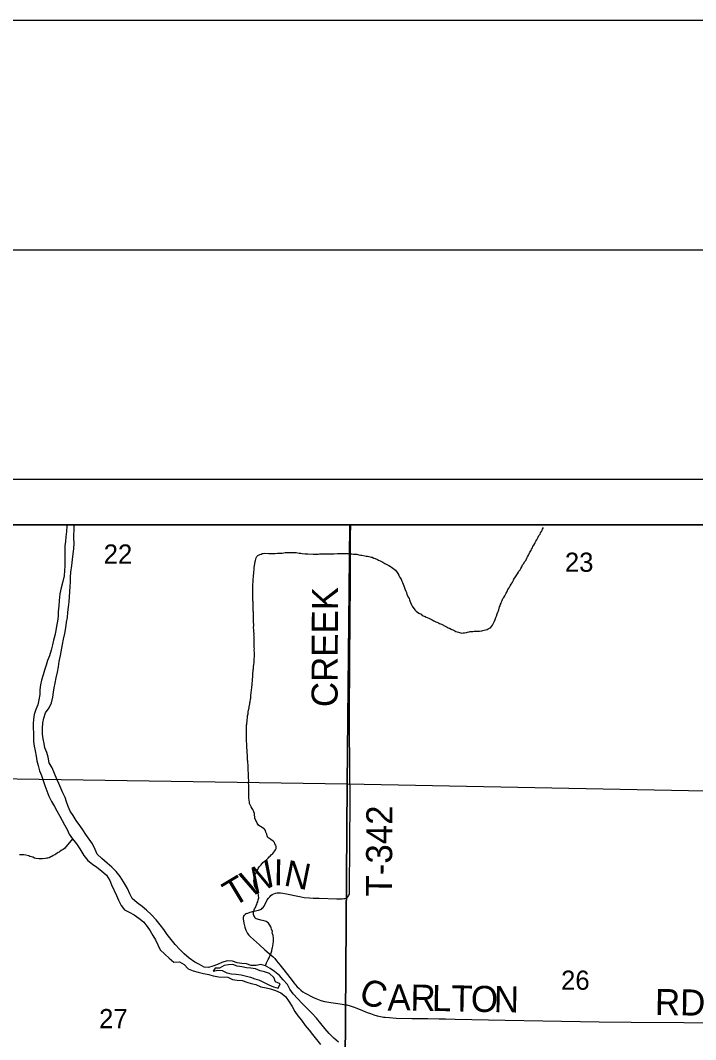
# Model space of a CAD drawing. Extents: x 0 to 34, y 0 to 22.
# Drawn here: x 6.788 to 8.26, y 19.778 to 22 of the extents above; entities that cross this region are included whole.
import ezdxf

# ---------------------------------------------------------------- set-up
doc = ezdxf.new("R2010")
doc.units = 0
for name, color, linetype in [('GM_X_Corporation', 7, 'Continuous'), ('GM_X_Major_River', 7, 'Continuous'), ('GM_X_Minor_River', 7, 'Continuous'), ('GM_X_Section_Text', 7, 'Continuous'), ('GM_X_Township_Road', 7, 'Continuous'), ('GM_X_Township_Road_Text', 7, 'Continuous'), ('SH_Border', 7, 'Continuous'), ('SH_Cut_Line', 7, 'Continuous'), ('SH_Data', 7, 'Continuous')]:
    doc.layers.add(name, color=color, linetype=linetype)

msp = doc.modelspace()

# ---------------------------------------------------------------- linework, layer by layer
at = {"layer": 'GM_X_Corporation'}
msp.add_lwpolyline([(8.9, 20.9), (3.5231, 20.9), (3.5228, 20.8664), (3.5224, 20.8347), (3.5214, 20.7384), (3.5203, 20.6635), (3.5197, 20.5949), (3.5191, 20.549), (3.5181, 20.4924), (3.5169, 20.4148), (3.5163, 20.3526), (3.5155, 20.3135), (3.5145, 20.2333), (3.5137, 20.1344), (3.5125, 20.0737), (3.5112, 20.0053), (3.511, 19.9493), (3.5095, 19.8637), (3.5082, 19.7748)], dxfattribs=at)
for points in [[(7.5063, 20.9), (6.4979, 20.9), (6.4927, 20.3511), (7.5004, 20.336)], [(8.5096, 20.9), (7.5063, 20.9), (7.5004, 20.336), (8.5046, 20.316)], [(6.4927, 20.3511), (7.5004, 20.336), (7.4935, 19.3206), (6.4855, 19.3379)], [(7.5004, 20.336), (8.5046, 20.316), (8.496, 19.3116), (7.4935, 19.3206)]]:
    msp.add_lwpolyline(points, close=True, dxfattribs=at)
at = {"layer": 'GM_X_Major_River'}
for points in [[(6.89, 20.9), (6.8897, 20.8971), (6.8887, 20.8861), (6.8873, 20.8743), (6.8864, 20.8641), (6.8851, 20.8543), (6.8849, 20.8425), (6.8851, 20.833), (6.8852, 20.8205), (6.885, 20.811), (6.8845, 20.8007), (6.8835, 20.7893), (6.8806, 20.7765), (6.8769, 20.7633), (6.8744, 20.75), (6.873, 20.7356), (6.872, 20.7235), (6.871, 20.711), (6.8709, 20.7015), (6.8695, 20.6901), (6.8674, 20.6795), (6.8653, 20.6697), (6.8633, 20.6591), (6.8608, 20.6489), (6.8587, 20.639), (6.8551, 20.6273), (6.8518, 20.6145), (6.8478, 20.6043), (6.8442, 20.5945), (6.8406, 20.5835), (6.8382, 20.5733), (6.8345, 20.5616), (6.8324, 20.5518), (6.8311, 20.5408), (6.8305, 20.5302), (6.8284, 20.5185), (6.8263, 20.5082), (6.822, 20.4977), (6.8187, 20.4867), (6.8166, 20.4765), (6.8161, 20.4667), (6.8159, 20.4572), (6.8168, 20.4469), (6.8173, 20.4279), (6.8186, 20.418), (6.8207, 20.4073), (6.8227, 20.3963), (6.8244, 20.3856), (6.8269, 20.3757), (6.8301, 20.3642), (6.8341, 20.3539), (6.8377, 20.3432), (6.842, 20.3317), (6.846, 20.3206), (6.8507, 20.3088), (6.8562, 20.2973), (6.8625, 20.2865), (6.868, 20.2766), (6.8742, 20.2654), (6.8845, 20.2463), (6.89, 20.2359), (6.8947, 20.2263), (6.9017, 20.2155), (6.9103, 20.2051), (6.918, 20.194), (6.9269, 20.1794), (6.9354, 20.1686), (6.9455, 20.1604), (6.9552, 20.1538), (6.965, 20.1464), (6.9758, 20.1367), (6.9835, 20.1252), (6.9872, 20.1152), (6.9981, 20.0922), (7.0025, 20.0819), (7.008, 20.0708), (7.0154, 20.0612), (7.0255, 20.0556), (7.036, 20.0501), (7.0465, 20.0431), (7.057, 20.0346), (7.0648, 20.0245), (7.0711, 20.0149), (7.0769, 20.0053), (7.0825, 19.9957), (7.0876, 19.985), (7.0931, 19.9739), (7.1031, 19.9642), (7.1128, 19.9553), (7.1229, 19.9468), (7.1351, 19.9477), (7.1456, 19.9418), (7.1541, 19.9321)], [(7.261, 19.9457), (7.2504, 19.9489), (7.2391, 19.9495), (7.2276, 19.9459), (7.2177, 19.942), (7.2081, 19.9383), (7.1982, 19.9355), (7.1887, 19.936), (7.1786, 19.9415), (7.1688, 19.9467), (7.1561, 19.9553), (7.1453, 19.9649), (7.1352, 19.975), (7.1259, 19.9854), (7.1166, 19.9966), (7.1085, 20.007), (7.1007, 20.0182), (7.0929, 20.0282), (7.084, 20.0394), (7.0732, 20.0506), (7.0635, 20.0603), (7.0534, 20.0684), (7.043, 20.0766), (7.0318, 20.0855), (7.027, 20.0959), (7.0215, 20.1077), (7.0131, 20.1223), (7.0057, 20.1339), (6.9968, 20.1443), (6.9875, 20.1543), (6.9774, 20.1629), (6.9655, 20.173), (6.9554, 20.1823), (6.951, 20.1926), (6.9452, 20.2049), (6.9382, 20.2153), (6.9311, 20.2253), (6.9245, 20.2353), (6.9182, 20.2449), (6.9101, 20.2556), (6.9031, 20.2664), (6.8972, 20.2764), (6.8928, 20.286), (6.8892, 20.2963), (6.8856, 20.3059), (6.8812, 20.3158), (6.8765, 20.3262), (6.8721, 20.3365), (6.8677, 20.3461), (6.8576, 20.3706), (6.8509, 20.3813), (6.8492, 20.3935), (6.846, 20.4038), (6.842, 20.4141), (6.8403, 20.4237), (6.8382, 20.434), (6.8369, 20.4439), (6.8364, 20.456), (6.8374, 20.4685), (6.8394, 20.4788), (6.8434, 20.4905), (6.8509, 20.5017), (6.8564, 20.5126), (6.8589, 20.5243), (6.8606, 20.5353), (6.8623, 20.5452), (6.864, 20.5554), (6.8665, 20.5671), (6.869, 20.5792), (6.8711, 20.5906), (6.8732, 20.6023), (6.8761, 20.6152), (6.8803, 20.6394), (6.8825, 20.6508), (6.8853, 20.6636), (6.8875, 20.6761), (6.8892, 20.6882), (6.8909, 20.6984), (6.8919, 20.7098), (6.8932, 20.7208), (6.8946, 20.7326), (6.8955, 20.7432), (6.8967, 20.7659), (6.8973, 20.7758), (6.8975, 20.7861), (6.8984, 20.797), (6.9002, 20.8118), (6.902, 20.8247), (6.9033, 20.8372), (6.9047, 20.8482), (6.9053, 20.86), (6.9051, 20.8713), (6.9056, 20.896), (6.9054, 20.9)], [(7.1541, 19.9321), (7.1651, 19.9281), (7.176, 19.9253), (7.1873, 19.9224), (7.1987, 19.9199), (7.2085, 19.9171), (7.2206, 19.9146), (7.2407, 19.9142), (7.2508, 19.9091), (7.2607, 19.9074), (7.2717, 19.9068), (7.2815, 19.9036), (7.2913, 19.9007), (7.3015, 19.8983), (7.3124, 19.8935), (7.3237, 19.891), (7.3336, 19.8885), (7.3441, 19.8853), (7.3558, 19.8798), (7.3663, 19.872), (7.3744, 19.8604), (7.3803, 19.8505), (7.3865, 19.8397), (7.3932, 19.8301), (7.4006, 19.8205), (7.4091, 19.8089), (7.4177, 19.7989), (7.4251, 19.7893), (7.434, 19.7785), (7.4425, 19.7673)], [(7.2083, 19.9273), (7.2186, 19.9294), (7.2284, 19.9288), (7.2382, 19.9234), (7.2484, 19.9213), (7.2587, 19.9211), (7.2692, 19.919), (7.2896, 19.914), (7.2994, 19.9108), (7.3096, 19.9076), (7.3194, 19.9029), (7.3299, 19.8973), (7.3401, 19.893), (7.3503, 19.8901), (7.3543, 19.8999), (7.3445, 19.9039), (7.3409, 19.9138), (7.3311, 19.9224), (7.3206, 19.926), (7.3108, 19.9281), (7.3006, 19.9321), (7.2908, 19.9338), (7.2813, 19.9343), (7.2707, 19.9364), (7.2609, 19.9385), (7.2511, 19.9417), (7.2416, 19.9411), (7.2321, 19.9398)], [(7.2321, 19.9398), (7.2225, 19.9335), (7.213, 19.9337), (7.2083, 19.9273)], [(7.4817, 19.7727), (7.4712, 19.7812), (7.4612, 19.7916), (7.4519, 19.8024), (7.443, 19.8132), (7.4333, 19.8248), (7.424, 19.8352), (7.4128, 19.8464), (7.4024, 19.8569), (7.3931, 19.8669), (7.3827, 19.8778), (7.3753, 19.8878), (7.3702, 19.8985), (7.3609, 19.9082), (7.3527, 19.9178), (7.3422, 19.9264), (7.3325, 19.9334), (7.3227, 19.9392), (7.3122, 19.9421), (7.3019, 19.9396), (7.2916, 19.9394), (7.2814, 19.943), (7.2712, 19.944), (7.261, 19.9457)]]:
    msp.add_lwpolyline(points, dxfattribs=at)
at = {"layer": 'GM_X_Minor_River'}
for points in [[(7.8348, 20.7273), (7.836, 20.7299), (7.8369, 20.7326), (7.8385, 20.7356), (7.8397, 20.7394), (7.8417, 20.7416), (7.8438, 20.7457), (7.8466, 20.751), (7.8482, 20.7532), (7.8502, 20.757), (7.8507, 20.7592), (7.8538, 20.7633), (7.8555, 20.7671), (7.8575, 20.7712), (7.8599, 20.7738), (7.8627, 20.7795), (7.8639, 20.7817), (7.8671, 20.7866), (7.8687, 20.7888), (7.8715, 20.7937), (7.8739, 20.7971), (7.8748, 20.7993), (7.8775, 20.8023), (7.8788, 20.8053), (7.8808, 20.8087), (7.8828, 20.8128), (7.8848, 20.8154), (7.8876, 20.8207), (7.8896, 20.8229), (7.8917, 20.8274), (7.8933, 20.8308), (7.8953, 20.8345), (7.8969, 20.8368), (7.8985, 20.8409), (7.9013, 20.8443), (7.9022, 20.8473), (7.9042, 20.8503), (7.9054, 20.8529), (7.9074, 20.8559), (7.9094, 20.8593), (7.9102, 20.8615), (7.9119, 20.8649), (7.9139, 20.8679), (7.9151, 20.8705), (7.9167, 20.8732), (7.9183, 20.8769), (7.9207, 20.8803), (7.9219, 20.8829), (7.9239, 20.8859), (7.9252, 20.8885), (7.9264, 20.8912), (7.928, 20.8942)], [(7.2974, 20.6602), (7.2975, 20.6629), (7.2973, 20.6678), (7.2969, 20.6701), (7.2967, 20.6774), (7.2968, 20.6812), (7.2969, 20.6834), (7.2967, 20.6884), (7.2963, 20.6911), (7.2964, 20.6933), (7.2961, 20.6983), (7.2962, 20.7013), (7.296, 20.707), (7.2961, 20.7097), (7.2957, 20.712), (7.2959, 20.7177), (7.2956, 20.7215), (7.2957, 20.7241), (7.2954, 20.7295), (7.2955, 20.7325), (7.2952, 20.7348), (7.2949, 20.7382), (7.295, 20.7428), (7.2947, 20.7451), (7.2949, 20.7515), (7.2946, 20.7569), (7.295, 20.772), (7.2955, 20.7743), (7.2957, 20.7823), (7.2962, 20.7872), (7.2967, 20.7903), (7.2968, 20.7941), (7.2968, 20.7967), (7.2978, 20.8035), (7.2979, 20.8066), (7.2988, 20.8119), (7.2993, 20.8153), (7.3002, 20.8206), (7.3006, 20.8228), (7.3023, 20.8281), (7.3035, 20.8311), (7.3055, 20.8337), (7.3102, 20.8359), (7.3129, 20.8366), (7.3152, 20.8377), (7.3175, 20.8376), (7.3214, 20.8383), (7.3298, 20.8381), (7.3344, 20.8376), (7.3371, 20.8379), (7.3402, 20.8378), (7.3437, 20.8381), (7.3487, 20.8384), (7.3529, 20.8387), (7.3552, 20.8386), (7.3587, 20.8389), (7.3625, 20.8392), (7.3656, 20.8399), (7.3698, 20.8398), (7.3729, 20.8401), (7.3891, 20.8397), (7.3959, 20.8388), (7.3998, 20.8383), (7.4021, 20.8378), (7.4086, 20.8373), (7.4147, 20.8368), (7.4266, 20.8365), (7.4301, 20.8364), (7.4339, 20.8367), (7.437, 20.8366), (7.4405, 20.8369), (7.4431, 20.8368), (7.4466, 20.8371), (7.4516, 20.837), (7.4555, 20.8373), (7.4624, 20.8371), (7.4662, 20.8374), (7.4716, 20.8373), (7.4793, 20.8375), (7.4831, 20.8378), (7.4862, 20.8377), (7.4893, 20.8376), (7.4916, 20.8379), (7.5027, 20.8377), (7.5077, 20.8372), (7.5104, 20.8371), (7.5142, 20.8366), (7.5165, 20.8366), (7.5188, 20.8361), (7.5219, 20.8361), (7.5257, 20.8352), (7.5299, 20.8343), (7.5326, 20.8339), (7.5387, 20.8326), (7.5421, 20.8321), (7.5448, 20.8317), (7.5479, 20.8313), (7.5528, 20.83), (7.5551, 20.8296), (7.5586, 20.8279), (7.5612, 20.8267)], [(7.5612, 20.8267), (7.5665, 20.8247), (7.5688, 20.8231), (7.5722, 20.8215), (7.5753, 20.8203), (7.5783, 20.8187), (7.5825, 20.8163), (7.5866, 20.814), (7.5912, 20.8116), (7.5949, 20.8092), (7.5972, 20.808), (7.6002, 20.806), (7.6032, 20.8037), (7.6059, 20.8017), (7.6096, 20.7963), (7.6107, 20.794), (7.6129, 20.7905), (7.6154, 20.7855), (7.618, 20.7816), (7.6195, 20.7778), (7.6209, 20.7747), (7.6227, 20.7709), (7.6242, 20.7674), (7.6249, 20.7651), (7.6263, 20.7609), (7.6285, 20.7559), (7.6299, 20.7525), (7.6306, 20.749), (7.6335, 20.7429), (7.6353, 20.7394), (7.6361, 20.7371), (7.6371, 20.7348), (7.6382, 20.731), (7.6407, 20.7256), (7.6422, 20.7229), (7.6433, 20.7206), (7.6467, 20.7171), (7.6478, 20.7148), (7.6508, 20.7124), (7.6534, 20.7101), (7.6568, 20.7077), (7.6617, 20.7053), (7.664, 20.703), (7.6704, 20.7005), (7.6727, 20.6993), (7.675, 20.6985), (7.6784, 20.6969), (7.686, 20.6929), (7.6894, 20.6913), (7.6939, 20.6889), (7.6962, 20.6881), (7.6993, 20.6865), (7.7019, 20.6849), (7.7057, 20.6837), (7.7156, 20.6785), (7.7182, 20.6773), (7.7205, 20.6757), (7.7232, 20.6749), (7.7269, 20.6729), (7.7323, 20.6705), (7.7349, 20.6693), (7.7372, 20.6681), (7.7402, 20.6673), (7.7429, 20.6661), (7.7452, 20.6656), (7.7482, 20.6648), (7.7505, 20.6644), (7.7532, 20.6647), (7.7563, 20.665), (7.7602, 20.6656), (7.7625, 20.6664), (7.766, 20.667), (7.7687, 20.6677), (7.7718, 20.668), (7.7745, 20.668), (7.7772, 20.6683), (7.7821, 20.6682), (7.7864, 20.6684), (7.7891, 20.6687), (7.7937, 20.6694), (7.7964, 20.6697), (7.7991, 20.6704), (7.8018, 20.6715), (7.8053, 20.6725), (7.808, 20.6736), (7.8104, 20.6751), (7.8131, 20.6761), (7.8151, 20.6784), (7.8171, 20.6817), (7.8195, 20.6859), (7.8212, 20.6904), (7.8228, 20.6938), (7.8244, 20.6983), (7.8261, 20.7013), (7.8277, 20.7066), (7.8286, 20.7096), (7.8302, 20.713), (7.831, 20.7152), (7.8327, 20.7213), (7.834, 20.7239), (7.8348, 20.7273)], [(7.3128, 20.2421), (7.3098, 20.2437), (7.3075, 20.2453), (7.3057, 20.2476), (7.3046, 20.2503), (7.3027, 20.2534), (7.3017, 20.256), (7.2995, 20.2607), (7.2995, 20.2629), (7.2989, 20.2679), (7.2982, 20.2709), (7.2968, 20.2744), (7.2961, 20.2767), (7.2946, 20.2794), (7.2935, 20.2817), (7.2913, 20.2859), (7.2895, 20.2887), (7.288, 20.2925), (7.2873, 20.2952), (7.2867, 20.3005), (7.2864, 20.3036), (7.2865, 20.3058), (7.2862, 20.3112), (7.2863, 20.3134), (7.286, 20.3157), (7.2862, 20.3252), (7.2859, 20.3275), (7.286, 20.3321), (7.2858, 20.3378), (7.2859, 20.3427), (7.2857, 20.3488), (7.2858, 20.3515), (7.2855, 20.3545), (7.2852, 20.3579), (7.285, 20.3652), (7.2847, 20.3697), (7.2844, 20.3732), (7.2845, 20.3758), (7.2839, 20.3827), (7.284, 20.3853), (7.2836, 20.3876), (7.2834, 20.3933), (7.2835, 20.3964), (7.2832, 20.399), (7.2829, 20.4025), (7.2827, 20.4093), (7.2821, 20.4143), (7.2821, 20.4173), (7.2815, 20.4227), (7.2813, 20.4287), (7.281, 20.4314), (7.2811, 20.4379), (7.2808, 20.4409), (7.2811, 20.4497), (7.2812, 20.4527), (7.2814, 20.4633), (7.2819, 20.466), (7.282, 20.4683), (7.2824, 20.4717), (7.2826, 20.4762), (7.283, 20.4789), (7.2835, 20.4842), (7.2844, 20.4884), (7.2849, 20.4906), (7.2849, 20.4929), (7.2862, 20.499), (7.2867, 20.5016), (7.2871, 20.5039), (7.2885, 20.5103), (7.2885, 20.5126), (7.2893, 20.5148), (7.2899, 20.5205), (7.2903, 20.5228), (7.2908, 20.5277), (7.2914, 20.5346), (7.2923, 20.5391), (7.2925, 20.5467), (7.2934, 20.5512), (7.2935, 20.5558), (7.294, 20.5588), (7.294, 20.5615), (7.2941, 20.5638), (7.2946, 20.5691), (7.2951, 20.5729), (7.2952, 20.5759), (7.2957, 20.5812), (7.2958, 20.5839), (7.2962, 20.5861), (7.2967, 20.5903), (7.2973, 20.5964), (7.2977, 20.5994), (7.2983, 20.6214), (7.2981, 20.6268), (7.2982, 20.6302), (7.2979, 20.6329), (7.2981, 20.6416), (7.2979, 20.6469), (7.2979, 20.6492), (7.2977, 20.6553), (7.2978, 20.6576), (7.2974, 20.6602)], [(7.3227, 19.9392), (7.3237, 19.9434), (7.3245, 19.9457), (7.3269, 19.9498), (7.3282, 19.9525), (7.3302, 19.9566), (7.3314, 19.9588), (7.3326, 19.9618), (7.3343, 19.9652), (7.3355, 19.9698), (7.3364, 19.972), (7.3372, 19.9766), (7.3377, 19.9792), (7.3385, 19.9815), (7.3395, 19.9875), (7.34, 19.9917), (7.3401, 19.997), (7.3398, 19.9993), (7.3392, 20.005), (7.3374, 20.0111), (7.3375, 20.0138), (7.3357, 20.0188), (7.3346, 20.0218), (7.3339, 20.0241), (7.3321, 20.0276), (7.3302, 20.0299), (7.3287, 20.0323), (7.3265, 20.0338), (7.3242, 20.0354), (7.3216, 20.0366), (7.3189, 20.0374), (7.3162, 20.0379), (7.3124, 20.0387), (7.3101, 20.0392), (7.3074, 20.0396), (7.3048, 20.0404), (7.3021, 20.0416), (7.2998, 20.0432), (7.2984, 20.0463), (7.2969, 20.0486), (7.2962, 20.0509), (7.2963, 20.0532), (7.2967, 20.0558), (7.2972, 20.0581), (7.2988, 20.063), (7.3004, 20.066), (7.3021, 20.0702), (7.3037, 20.0724), (7.3046, 20.0762), (7.3058, 20.0788), (7.3066, 20.0826), (7.3071, 20.0849), (7.3079, 20.0875), (7.3076, 20.0913), (7.3073, 20.094), (7.3066, 20.0966), (7.3048, 20.1001), (7.3034, 20.1047), (7.3019, 20.1074), (7.3001, 20.1101), (7.2986, 20.1132), (7.2983, 20.1162), (7.2976, 20.1197), (7.2974, 20.1246), (7.2975, 20.1277), (7.2984, 20.1333), (7.2996, 20.1371), (7.3013, 20.1405), (7.3026, 20.1454), (7.3049, 20.1476), (7.3066, 20.1514), (7.3089, 20.1544), (7.3109, 20.1566), (7.3129, 20.1592), (7.3169, 20.1641), (7.3204, 20.1674), (7.3239, 20.1696), (7.3283, 20.1733), (7.3307, 20.1766), (7.333, 20.1781), (7.335, 20.1807), (7.3382, 20.1837), (7.3429, 20.1896), (7.3445, 20.1919), (7.3454, 20.1945), (7.3458, 20.1968), (7.3455, 20.1991), (7.3448, 20.2021), (7.343, 20.2052), (7.3419, 20.2079), (7.3389, 20.2106), (7.3344, 20.2146), (7.3298, 20.217), (7.3276, 20.2189), (7.3261, 20.2227), (7.3251, 20.2258), (7.3233, 20.2304), (7.3226, 20.2339), (7.3204, 20.2366), (7.3181, 20.2385), (7.3128, 20.2421)], [(6.9017, 20.2155), (6.8842, 20.1947), (6.8818, 20.1929), (6.8787, 20.191), (6.8752, 20.1889), (6.8732, 20.1866), (6.8709, 20.1859), (6.8685, 20.1845), (6.8654, 20.1826), (6.8631, 20.1808), (6.8596, 20.1794), (6.8572, 20.1775), (6.8549, 20.1768), (6.851, 20.1746), (6.8483, 20.1739), (6.846, 20.1736), (6.8429, 20.1729), (6.8367, 20.1723), (6.8325, 20.172), (6.8286, 20.1721), (6.8225, 20.173), (6.8191, 20.1739), (6.8157, 20.1755), (6.8126, 20.1763), (6.8092, 20.1776), (6.8065, 20.1788), (6.8004, 20.1804), (6.7958, 20.1809), (6.7866, 20.1812)]]:
    msp.add_lwpolyline(points, dxfattribs=at)
at = {"layer": 'GM_X_Township_Road'}
for points in [[(7.2808, 20.0527), (7.2838, 20.054), (7.2889, 20.0557), (7.2973, 20.058), (7.307, 20.0603), (7.3114, 20.0618), (7.3137, 20.0628), (7.3156, 20.0643), (7.3172, 20.0662), (7.3188, 20.0686), (7.3236, 20.0778), (7.3264, 20.0827), (7.3289, 20.0862), (7.3317, 20.0896), (7.3344, 20.0921), (7.3374, 20.0943), (7.3407, 20.096), (7.3442, 20.0972), (7.3479, 20.098), (7.3516, 20.0983), (7.3553, 20.0982), (7.3601, 20.0977), (7.3686, 20.0958), (7.3929, 20.0905), (7.4001, 20.0891), (7.4069, 20.0881), (7.4187, 20.0871), (7.4267, 20.0866), (7.4398, 20.0861), (7.4777, 20.0853), (7.4895, 20.0851), (7.4932, 20.0854), (7.4957, 20.0858), (7.4984, 20.0867), (7.5007, 20.0881), (7.5021, 20.0894), (7.5035, 20.0913), (7.5044, 20.0929), (7.5052, 20.0953), (7.5057, 20.0983), (7.5059, 20.1027), (7.5059, 20.1238), (7.506, 20.1846), (7.5063, 20.2128), (7.507, 20.2921), (7.5056, 20.4564), (7.5064, 20.6318), (7.5069, 20.6682), (7.5072, 20.7185), (7.5074, 20.749), (7.5074, 20.8353), (7.5079, 20.8756), (7.5081, 20.9)], [(7.2808, 20.0527), (7.2782, 20.0512), (7.2764, 20.0497), (7.2754, 20.0484), (7.2745, 20.0466), (7.2741, 20.0441), (7.274, 20.0409), (7.2744, 20.0371), (7.2752, 20.0322), (7.2772, 20.0235), (7.2782, 20.0207), (7.2797, 20.0166), (7.2816, 20.0126), (7.2835, 20.0095), (7.2862, 20.006), (7.2899, 20.002), (7.3091, 19.9844), (7.3211, 19.9736), (7.3303, 19.966), (7.339, 19.9587), (7.3428, 19.9546), (7.3466, 19.9501), (7.3538, 19.9409), (7.3592, 19.9337), (7.3781, 19.9097), (7.3843, 19.9017), (7.3917, 19.8933), (7.3956, 19.8893), (7.3993, 19.886), (7.4039, 19.8826), (7.4089, 19.8794), (7.4116, 19.8779), (7.4145, 19.8764), (7.42, 19.8737), (7.4274, 19.8701), (7.4321, 19.8678), (7.4358, 19.8661), (7.4395, 19.8646), (7.4432, 19.8633), (7.4513, 19.8613), (7.4563, 19.8604), (7.465, 19.8592), (7.4851, 19.8561), (7.4973, 19.854)], [(7.4973, 19.854), (7.4994, 19.8536), (7.5073, 19.8517), (7.5139, 19.8497), (7.5215, 19.8469), (7.534, 19.8417), (7.544, 19.8373), (7.551, 19.8348), (7.5589, 19.8323), (7.5656, 19.8303), (7.573, 19.8285), (7.5764, 19.8278), (7.5799, 19.8272), (7.5832, 19.8268), (7.5921, 19.826), (7.6075, 19.8252), (7.6413, 19.8242), (7.676, 19.8239), (7.7008, 19.8237), (7.7145, 19.8234), (7.7356, 19.8229), (7.8449, 19.8204), (7.9268, 19.8189), (8.0494, 19.8169), (8.1194, 19.8161), (8.4646, 19.8139)]]:
    msp.add_lwpolyline(points, dxfattribs=at)
at = {"layer": 'SH_Border'}
msp.add_lwpolyline([(1.5, 21.5), (33.5, 21.5), (33.5, 0.5), (1.5, 0.5)], close=True, dxfattribs=at)
at = {"layer": 'SH_Cut_Line'}
msp.add_lwpolyline([(0, 0), (34, 0), (34, 22), (0, 22)], close=True, dxfattribs=at)
at = {"layer": 'SH_Data'}
for p, q in [((2, 21), (9, 21)), ((2.1, 20.9), (8.9, 20.9)), ((2.1, 20.9), (8.9, 20.9)), ((2.1, 20.9), (8.9, 20.9))]:
    msp.add_line(p, q, dxfattribs=at)

# ---------------------------------------------------------------- texts
at = {"layer": 'GM_X_Section_Text'}
for s, p in [('22', (6.9699, 20.8157)), ('23', (7.9749, 20.7979)), ('26', (7.9666, 19.8867)), ('27', (6.9599, 19.8029))]:
    msp.add_text(s, height=0.04186, rotation=0, dxfattribs=at).set_placement(p)
at = {"layer": 'GM_X_Township_Road_Text'}
for s, height, rotation, p in [('CREEK', 0.05682, 89.7976, (7.4796, 20.5029)), ('T-342', 0.05682, 89.7207, (7.5981, 20.0899)), ('W', 0.0568, 25.7435, (7.2873, 20.0874)), ('I', 0.0568, 359.3833, (7.3399, 20.1145)), ('N', 0.0568, 348.6293, (7.3604, 20.1146)), ('T', 0.0568, 31.0516, (7.2521, 20.0661)), ('C', 0.0568, 339.4547, (7.5226, 19.8617)), ('A', 0.0568, 0.2355, (7.5883, 19.8414)), ('R', 0.0568, 358.8954, (7.638, 19.8416)), ('L', 0.0568, 358.8943, (7.6846, 19.8407)), ('T', 0.0568, 358.8943, (7.7271, 19.8398)), ('O', 0.0568, 358.8955, (7.7696, 19.839)), ('N', 0.0568, 358.8955, (7.8196, 19.8381)), ('RD', 0.05682, 359.0128, (8.1707, 19.8319))]:
    msp.add_text(s, height=height, rotation=rotation, dxfattribs=at).set_placement(p)

doc.saveas('drawing.dxf')
